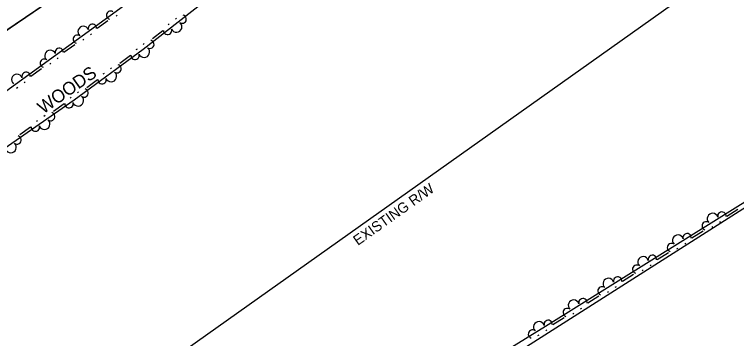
# Model space of a CAD drawing. Extents: x 1577032 to 1581865, y 611492 to 615011.
# Drawn here: x 1579944.1 to 1580168.3, y 613325.8 to 613426.5 of the extents above; entities that cross this region are included whole.
import ezdxf

# ---------------------------------------------------------------- set-up
doc = ezdxf.new("R2010")
doc.units = 0
for name, color, linetype in [('Exist Guardrail', 7, 'Continuous'), ('Exist Other Culture Fence Line', 7, 'Continuous'), ('Exist Right of Way Line', 7, 'Continuous'), ('Exist Right of Way Line Text', 7, 'Continuous'), ('Exist Vegetation Woods Line Text', 7, 'Continuous'), ('Old_Level_11', 7, 'Continuous'), ('Old_Level_7', 7, 'Continuous')]:
    doc.layers.add(name, color=color, linetype=linetype)

msp = doc.modelspace()

# ---------------------------------------------------------------- linework, layer by layer
at = {"layer": 'Exist Guardrail'}
msp.add_lwpolyline([(1580204.94, 613604.14), (1580176.13, 613584.66), (1580156.54, 613571.08), (1580137.28, 613557.36), (1580118.21, 613543.22), (1580106.98, 613535), (1580070.56, 613509.77), (1580039.34, 613487.9), (1579996.35, 613458.56), (1579960.14, 613434.1), (1579928.53, 613412.65), (1579891.13, 613387.42), (1579884.09, 613382.52), (1579876.58, 613377.52), (1579866.53, 613371.18), (1579856.35, 613364.93), (1579850.36, 613361.17), (1579845.45, 613357.94), (1579839.56, 613353.95), (1579830.4, 613347.61), (1579818.74, 613338.59)], dxfattribs=at)
at = {"layer": 'Exist Other Culture Fence Line'}
msp.add_line((1579947.54, 613224.25), (1580319.1, 613460.95), dxfattribs=at)
at = {"layer": 'Exist Right of Way Line'}
msp.add_line((1578304.92, 612120.6), (1580458.22, 613649.74), dxfattribs=at)
at = {"layer": 'Old_Level_11'}
for points in [[(1580156.06, 613559.3), (1580161.76, 613552.9), (1580150.95, 613543.94), (1580133.01, 613530.08), (1580113.63, 613514.92), (1580094.48, 613500.02), (1580075.04, 613484.95), (1580051.08, 613466.93), (1580027.89, 613449.31), (1580002.55, 613429.96), (1579984.13, 613415.59), (1579962.72, 613399.84), (1579922.89, 613372.21), (1579876.06, 613342.54), (1579870.92, 613340.95), (1579866.8, 613349.13), (1579884.06, 613361.44), (1579915.37, 613383.81), (1579973.43, 613425.83), (1580032.77, 613469.22), (1580081.59, 613504.98), (1580153.92, 613556.9)], [(1580057.96, 613298.21), (1580109, 613329.66), (1580175.07, 613370.87), (1580321.43, 613454.81)], [(1579969.82, 613422.2), (1579973.15, 613424.61)], [(1579975.71, 613425.97), (1579976.04, 613426.21)], [(1579994.49, 613425.23), (1579994.17, 613424.98)], [(1579992.23, 613423.46), (1579991.9, 613423.21)], [(1579967.74, 613420.19), (1579968.07, 613420.43)], [(1579990.22, 613421.38), (1579986.98, 613418.85)], [(1579965.41, 613418.5), (1579965.74, 613418.75)], [(1579984.46, 613417.41), (1579984.14, 613417.16)], [(1579959.52, 613414.75), (1579962.85, 613417.15)], [(1579982.21, 613415.7), (1579981.88, 613415.46)], [(1579957.44, 613412.73), (1579957.77, 613412.98)], [(1579980.14, 613413.67), (1579976.83, 613411.24)], [(1579955.11, 613411.05), (1579955.44, 613411.29)], [(1579949.22, 613407.3), (1579952.55, 613409.7)], [(1579974.28, 613409.87), (1579973.95, 613409.63)], [(1579971.96, 613408.17), (1579971.63, 613407.93)], [(1579947.14, 613405.28), (1579947.47, 613405.52)], [(1579969.89, 613406.14), (1579966.59, 613403.71)], [(1579944.81, 613403.6), (1579945.15, 613403.84)], [(1579964.03, 613402.34), (1579963.7, 613402.09)], [(1579961.74, 613400.66), (1579961.41, 613400.43)], [(1579959.62, 613398.69), (1579956.25, 613396.35)], [(1579953.66, 613395.05), (1579953.32, 613394.82)], [(1579951.3, 613393.42), (1579950.96, 613393.18)], [(1579949.18, 613391.44), (1579945.81, 613389.1)], [(1580165.28, 613363.8), (1580168.75, 613365.97)], [(1580163.05, 613361.93), (1580163.4, 613362.15)], [(1580154.49, 613357.07), (1580157.97, 613359.24)], [(1580160.62, 613360.41), (1580160.97, 613360.63)], [(1580152.27, 613355.2), (1580152.62, 613355.42)], [(1580143.7, 613350.34), (1580147.18, 613352.51)], [(1580149.84, 613353.68), (1580150.18, 613353.9)], [(1580141.48, 613348.48), (1580141.83, 613348.69)], [(1580132.92, 613343.61), (1580136.4, 613345.78)], [(1580139.05, 613346.95), (1580139.39, 613347.17)], [(1580130.7, 613341.75), (1580131.04, 613341.96)], [(1580122.13, 613336.89), (1580125.61, 613339.06)], [(1580128.26, 613340.23), (1580128.61, 613340.44)], [(1580119.91, 613335.02), (1580120.26, 613335.24)], [(1580111.34, 613330.16), (1580114.82, 613332.33)], [(1580117.47, 613333.5), (1580117.82, 613333.72)], [(1580109.12, 613328.29), (1580109.47, 613328.51)], [(1580106.67, 613326.78), (1580107.02, 613327)]]:
    msp.add_lwpolyline(points, dxfattribs=at)
for centre, radius, start, end in [((1579973.99, 613426.24), 1.3, 54.6108, 255.4074), ((1579996.22, 613425.02), 1.3, 236.3886, 77.1852), ((1579965.54, 613421.13), 1.69, 21.8564, 229.9289), ((1579968.35, 613422.15), 1.3, 356.6612, 197.4577), ((1579991.69, 613421.49), 1.3, 178.7222, 19.5187), ((1579994.46, 613422.61), 1.69, 203.9174, 51.9899), ((1579963.69, 613418.78), 1.3, 54.3276, 255.1242), ((1579986.19, 613417.2), 1.3, 236.3886, 77.1852), ((1579955.24, 613413.67), 1.69, 21.8564, 229.9289), ((1579958.05, 613414.69), 1.3, 356.6612, 197.4577), ((1579984.41, 613414.78), 1.69, 202.2987, 50.3712), ((1579981.61, 613413.74), 1.3, 177.1034, 17.9), ((1579953.4, 613411.33), 1.3, 54.3276, 255.1242), ((1579976, 613409.61), 1.3, 234.7699, 75.5664), ((1579947.75, 613407.24), 1.3, 356.6612, 197.4577), ((1579974.17, 613407.25), 1.69, 202.2987, 50.3712), ((1579944.94, 613406.22), 1.69, 21.8564, 229.9289), ((1579971.37, 613406.21), 1.3, 177.1034, 17.9), ((1579965.75, 613402.07), 1.3, 234.7699, 75.5664), ((1579963.93, 613399.71), 1.69, 202.2987, 50.3712), ((1579961.1, 613398.72), 1.3, 175.5268, 16.3234), ((1579955.37, 613394.74), 1.3, 233.1933, 73.9898), ((1579953.48, 613392.43), 1.69, 200.7221, 48.7945), ((1579950.65, 613391.47), 1.3, 175.5268, 16.3234), ((1579944.93, 613387.49), 1.3, 233.1933, 73.9898), ((1579943.03, 613385.18), 1.69, 200.7221, 48.7945), ((1580160.93, 613363.02), 1.69, 17.9187, 225.9912), ((1580163.8, 613363.84), 1.3, 352.7235, 193.52), ((1580158.93, 613360.81), 1.3, 50.3899, 251.1865), ((1580150.14, 613356.29), 1.69, 17.9187, 225.9912), ((1580153.01, 613357.12), 1.3, 352.7235, 193.52), ((1580148.14, 613354.08), 1.3, 50.3899, 251.1865), ((1580139.35, 613349.56), 1.69, 17.9187, 225.9912), ((1580142.22, 613350.39), 1.3, 352.7235, 193.52), ((1580137.35, 613347.35), 1.3, 50.3899, 251.1865), ((1580128.57, 613342.84), 1.69, 17.9187, 225.9912), ((1580131.44, 613343.66), 1.3, 352.7235, 193.52), ((1580126.57, 613340.62), 1.3, 50.3899, 251.1865), ((1580117.78, 613336.11), 1.69, 17.9187, 225.9912), ((1580120.65, 613336.93), 1.3, 352.7235, 193.52), ((1580115.78, 613333.89), 1.3, 50.3899, 251.1865), ((1580106.99, 613329.39), 1.69, 17.6074, 225.6799), ((1580109.86, 613330.2), 1.3, 352.7235, 193.52), ((1580104.98, 613327.18), 1.3, 50.0786, 250.8752)]:
    msp.add_arc(centre, radius, start, end, dxfattribs=at)
at = {"layer": 'Old_Level_7'}
msp.add_lwpolyline([(1580204.41, 613605.7), (1580184.66, 613591.04), (1580164.93, 613576.99), (1580138.26, 613557.96), (1580109.19, 613537.33), (1580079.14, 613516.2), (1580044.46, 613491.82), (1580020.63, 613475.12), (1579980.8, 613448.19), (1579942.82, 613422.24), (1579900.08, 613391.73), (1579828.5, 613345.35)], dxfattribs=at)

# ---------------------------------------------------------------- texts
at = {"layer": 'Exist Right of Way Line Text'}
msp.add_text('EXISTING R/W', height=3.2, rotation=35.38, dxfattribs=at).set_placement((1580050.76, 613354.56))
at = {"layer": 'Exist Vegetation Woods Line Text'}
msp.add_text('WOODS', height=4, rotation=35.38, dxfattribs=at).set_placement((1579953.1, 613395.4))

doc.saveas('drawing.dxf')
